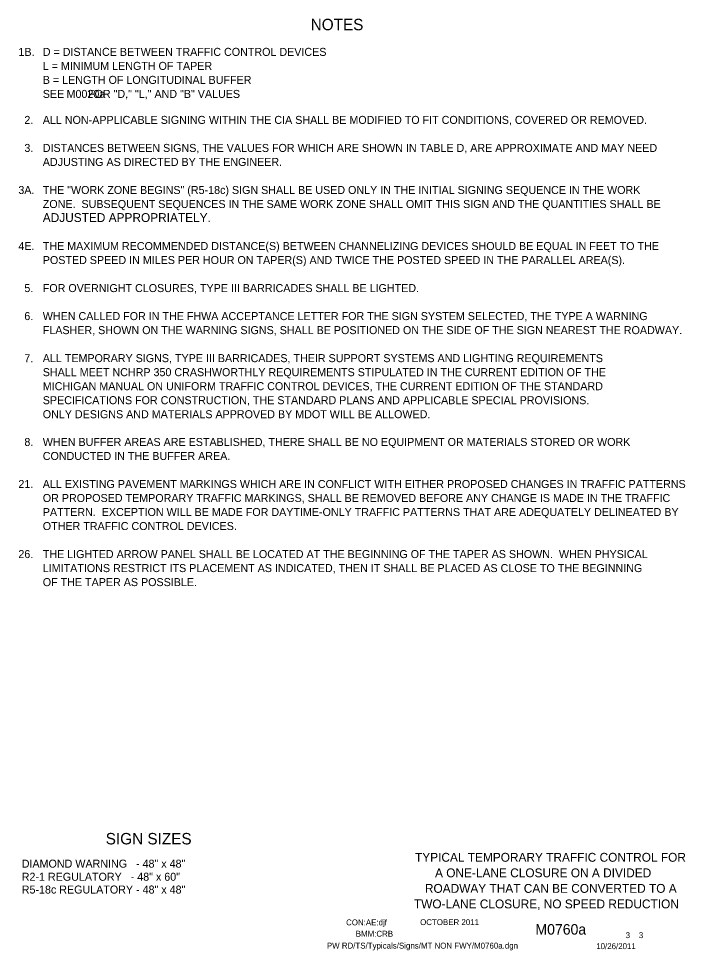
# Model space of a CAD drawing. Extents: x 16735 to 19504, y 6970 to 8243.
# Drawn here: x 18805 to 19504, y 7218 to 8195 of the extents above; entities that cross this region are included whole.
import ezdxf

# ---------------------------------------------------------------- set-up
doc = ezdxf.new("R2010")
doc.units = 0
for name, color, linetype in [('BORDER', 7, 'Continuous'), ('BORDER_SIGNAL_WO', 7, 'Continuous'), ('TYPICAL_TEXT_DIMEN_PR', 7, 'Continuous')]:
    doc.layers.add(name, color=color, linetype=linetype)

msp = doc.modelspace()

# ---------------------------------------------------------------- linework, layer by layer
at = {"layer": 'BORDER'}
msp.add_line((18938.25, 7341.25), (18938.25, 7341.25), dxfattribs=at)

# ---------------------------------------------------------------- texts
for s, p in [('TYPICAL TEMPORARY TRAFFIC CONTROL FOR', (19220.96, 7311.05)), ('A ONE-LANE CLOSURE ON A DIVIDED', (19241.94, 7294.75)), ('ROADWAY THAT CAN BE CONVERTED TO A', (19231.33, 7278.45)), ('TWO-LANE CLOSURE, NO SPEED REDUCTION ', (19219.79, 7262.15))]:
    msp.add_text(s, height=9.3, dxfattribs=at).set_placement(p)
at = {"layer": 'BORDER_SIGNAL_WO'}
for s, height, p in [('CON:AE:djf', 6.2, (19148.69, 7244.31)), ('    OCTOBER 2011    ', 6.2, (19217.08, 7244.59)), ('    M0760a   ', 11, (19330.86, 7234.63)), ('BMM:CRB   ', 6.2, (19158.81, 7232.42)), (' 3    3 ', 6.2, (19439.45, 7230.95)), ('PW RD/TS/Typicals/Signs/MT NON FWY/M0760a.dgn    ', 6.2, (19128.55, 7219.96)), ('10/26/2011    ', 6.2, (19410.93, 7219.38))]:
    msp.add_text(s, height=height, dxfattribs=at).set_placement(p)
at = {"layer": 'TYPICAL_TEXT_DIMEN_PR'}
for s, height, p in [('NOTES', 12, (19111.55, 8183.25)), ('1B.', 8.4, (18805.19, 8156.36)), ('D = DISTANCE BETWEEN TRAFFIC CONTROL DEVICES', 8.4, (18830.7, 8156.36)), ('L = MINIMUM LENGTH OF TAPER', 8.4, (18830.7, 8141.66)), ('B = LENGTH OF LONGITUDINAL BUFFER', 8.4, (18830.7, 8126.96)), ('SEE        FOR "D," "L," AND "B" VALUES', 8.4, (18830.7, 8112.26)), ('M0020a', 8.4, (18855.62, 8112.26)), ('2.', 8.4, (18811.39, 8085)), ('ALL NON-APPLICABLE SIGNING WITHIN THE CIA SHALL BE MODIFIED TO FIT CONDITIONS, COVERED OR REMOVED.', 8.4, (18830.7, 8085)), ('3.', 8.4, (18811.39, 8055.6)), ('DISTANCES BETWEEN SIGNS, THE VALUES FOR WHICH ARE SHOWN IN TABLE D, ARE APPROXIMATE AND MAY NEED', 8.4, (18830.7, 8055.6)), ('ADJUSTING AS DIRECTED BY THE ENGINEER.', 8.4, (18830.7, 8040.9)), ('3A.', 8.4, (18805.09, 8011.5)), ('THE "WORK ZONE BEGINS" (R5-18c) SIGN SHALL BE USED ONLY IN THE INITIAL SIGNING SEQUENCE IN THE WORK', 8.4, (18830.7, 8011.5)), ('ZONE.  SUBSEQUENT SEQUENCES IN THE SAME WORK ZONE SHALL OMIT THIS SIGN AND THE QUANTITIES SHALL BE', 8.4, (18830.7, 7996.8)), ('ADJUSTED APPROPRIATELY.', 9.3, (18830.7, 7982.1)), ('4E.', 8.4, (18805.13, 7952.7)), ('THE MAXIMUM RECOMMENDED DISTANCE(S) BETWEEN CHANNELIZING DEVICES SHOULD BE EQUAL IN FEET TO THE', 8.4, (18830.7, 7952.7)), ('POSTED SPEED IN MILES PER HOUR ON TAPER(S) AND TWICE THE POSTED SPEED IN THE PARALLEL AREA(S).', 8.4, (18830.7, 7938)), ('5.', 8.4, (18811.39, 7908.6)), ('FOR OVERNIGHT CLOSURES, TYPE III BARRICADES SHALL BE LIGHTED.', 8.4, (18830.7, 7908.6)), ('6.', 8.4, (18811.34, 7879.2)), ('WHEN CALLED FOR IN THE FHWA ACCEPTANCE LETTER FOR THE SIGN SYSTEM SELECTED, THE TYPE A WARNING ', 8.4, (18830.7, 7879.2)), ('FLASHER, SHOWN ON THE WARNING SIGNS, SHALL BE POSITIONED ON THE SIDE OF THE SIGN NEAREST THE ROADWAY.', 8.4, (18830.7, 7864.5)), ('7.', 8.4, (18811.34, 7835.07)), ('ALL TEMPORARY SIGNS, TYPE III BARRICADES, THEIR SUPPORT SYSTEMS AND LIGHTING REQUIREMENTS', 8.4, (18830.7, 7835.09)), ('SHALL MEET NCHRP 350 CRASHWORTHLY REQUIREMENTS STIPULATED IN THE CURRENT EDITION OF THE', 8.4, (18830.7, 7820.39)), ('MICHIGAN MANUAL ON UNIFORM TRAFFIC CONTROL DEVICES, THE CURRENT EDITION OF THE STANDARD', 8.4, (18830.7, 7805.69)), ('SPECIFICATIONS FOR CONSTRUCTION, THE STANDARD PLANS AND APPLICABLE SPECIAL PROVISIONS.', 8.4, (18830.7, 7790.99)), ('ONLY DESIGNS AND MATERIALS APPROVED BY MDOT WILL BE ALLOWED.', 8.4, (18830.7, 7776.29)), ('8.', 8.4, (18811.39, 7747.18)), ('WHEN BUFFER AREAS ARE ESTABLISHED, THERE SHALL BE NO EQUIPMENT OR MATERIALS STORED OR WORK     ', 8.4, (18830.7, 7747.18)), ('CONDUCTED IN THE BUFFER AREA.', 8.4, (18830.7, 7732.48)), ('21.', 8.4, (18805.14, 7703.08)), ('ALL EXISTING PAVEMENT MARKINGS WHICH ARE IN CONFLICT WITH EITHER PROPOSED CHANGES IN TRAFFIC PATTERNS', 8.4, (18830.7, 7703.08)), ('OR PROPOSED TEMPORARY TRAFFIC MARKINGS, SHALL BE REMOVED BEFORE ANY CHANGE IS MADE IN THE TRAFFIC', 8.4, (18830.7, 7688.38)), ('PATTERN.  EXCEPTION WILL BE MADE FOR DAYTIME-ONLY TRAFFIC PATTERNS THAT ARE ADEQUATELY DELINEATED BY', 8.4, (18830.7, 7673.68)), ('OTHER TRAFFIC CONTROL DEVICES.', 8.4, (18830.7, 7658.98)), ('26.', 8.4, (18805.09, 7629.58)), ('THE LIGHTED ARROW PANEL SHALL BE LOCATED AT THE BEGINNING OF THE TAPER AS SHOWN.  WHEN PHYSICAL', 8.4, (18830.7, 7629.58)), ('LIMITATIONS RESTRICT ITS PLACEMENT AS INDICATED, THEN IT SHALL BE PLACED AS CLOSE TO THE BEGINNING', 8.4, (18830.7, 7614.88)), ('OF THE TAPER AS POSSIBLE.', 8.4, (18830.7, 7600.18)), ('SIGN SIZES', 12, (18896.69, 7329.25)), ('DIAMOND WARNING   - 48" x 48"', 8.4, (18808.65, 7304.85)), ('R2-1 REGULATORY   - 48" x 60"', 8.4, (18808.65, 7291.11)), ('R5-18c REGULATORY - 48" x 48"', 8.4, (18808.65, 7277.67))]:
    msp.add_text(s, height=height, dxfattribs=at).set_placement(p)

doc.saveas('drawing.dxf')
